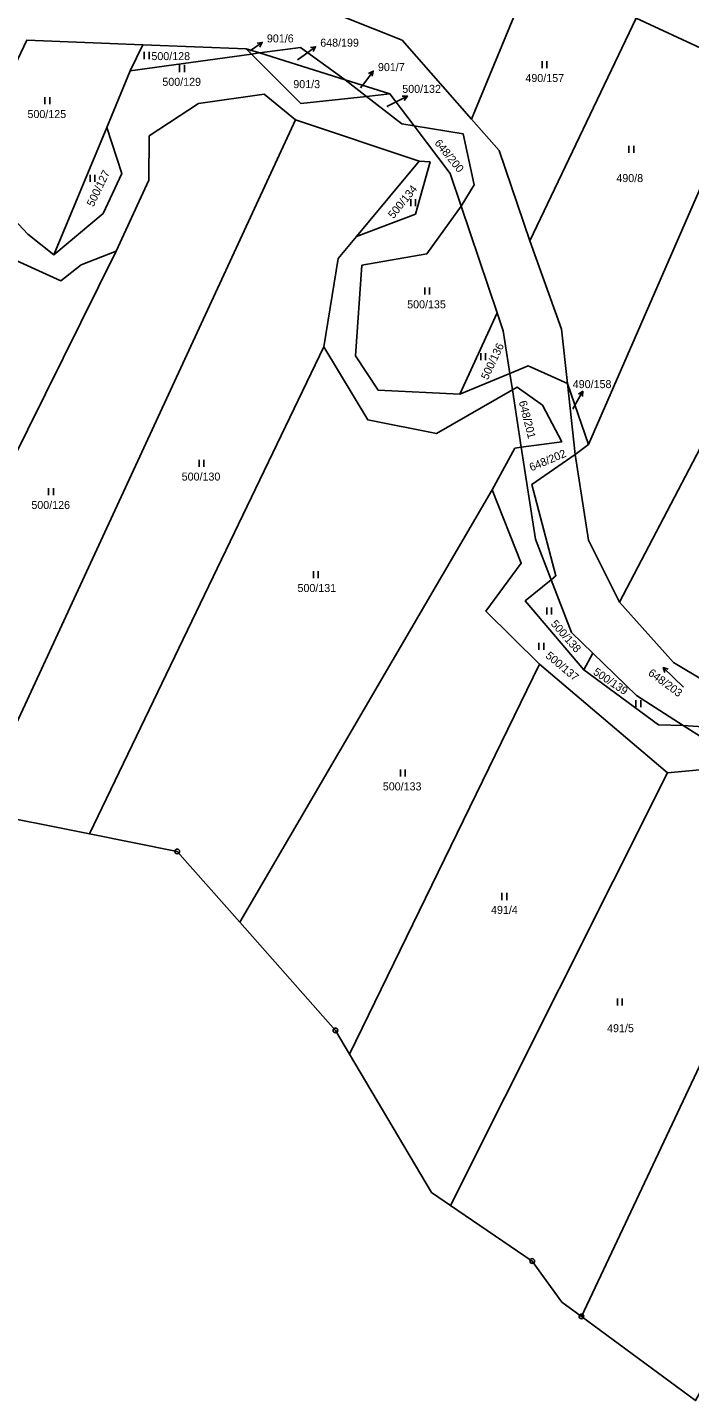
# Model space of a CAD drawing. Extents: x -654083 to -650132, y -1099819 to -1096699.
# Drawn here: x -650469.7 to -650329, y -1099108.4 to -1098816.8 of the extents above; entities that cross this region are included whole.
import ezdxf

# ---------------------------------------------------------------- set-up
doc = ezdxf.new("R2010")
doc.units = 0
for name, color, linetype in [('Geodetické body', 7, 'Continuous'), ('Obvody jako plochy', 7, 'Continuous'), ('Parcelní čísla', 7, 'Continuous'), ('Prvky pro prodl_ par_ č_', 7, 'Continuous'), ('Značky kultur', 7, 'Continuous')]:
    doc.layers.add(name, color=color, linetype=linetype)

msp = doc.modelspace()

# ---------------------------------------------------------------- linework, layer by layer
at = {"layer": 'Geodetické body'}
for centre, radius in [((-650437.89, -1098991.78), 0.5), ((-650437.89, -1098991.78), 0.001), ((-650404.24, -1099029.82), 0.5), ((-650404.24, -1099029.82), 0.001), ((-650362.41, -1099078.79), 0.5), ((-650362.41, -1099078.79), 0.001), ((-650351.95, -1099090.56), 0.5), ((-650351.95, -1099090.56), 0.5), ((-650351.95, -1099090.56), 0.001), ((-650351.95, -1099090.56), 0.001)]:
    msp.add_circle(centre, radius, dxfattribs=at)
at = {"layer": 'Obvody jako plochy'}
for points in [[(-650359.84, -1098798.83), (-650375.33, -1098836.22), (-650390.08, -1098819.48), (-650407.38, -1098812.55), (-650376.79, -1098746.23)], [(-650303.75, -1098798.96), (-650315.83, -1098826.13), (-650340.3, -1098814.8), (-650321.58, -1098776.26)], [(-650359.84, -1098798.83), (-650357.31, -1098806.74), (-650340.3, -1098814.8), (-650362.89, -1098862.05), (-650369.42, -1098842.92), (-650375.33, -1098836.22)], [(-650340.3, -1098814.8), (-650315.83, -1098826.13), (-650350.43, -1098905.37), (-650354.89, -1098892.38), (-650356.22, -1098880.84), (-650362.89, -1098862.05)], [(-650478.84, -1098838.29), (-650475.67, -1098854.31), (-650469.69, -1098860.68), (-650464.15, -1098865.04), (-650452.84, -1098838.04), (-650447.9, -1098825.96), (-650445.19, -1098820.41), (-650469.84, -1098819.44)], [(-650423.24, -1098821.28), (-650422.11, -1098822.41), (-650447.9, -1098825.96), (-650445.19, -1098820.41)], [(-650422.11, -1098822.41), (-650420.4, -1098822.17), (-650423.24, -1098821.28)], [(-650402.2, -1098827.88), (-650397.65, -1098831.4), (-650411.63, -1098832.89), (-650422.11, -1098822.41), (-650420.4, -1098822.17)], [(-650402.2, -1098827.88), (-650420.4, -1098822.17), (-650411.67, -1098821)], [(-650397.65, -1098831.4), (-650392.68, -1098830.87), (-650402.2, -1098827.88)], [(-650290.82, -1098837.74), (-650343.84, -1098938.87), (-650350.47, -1098925.67), (-650353.29, -1098907.45), (-650350.43, -1098905.37), (-650315.83, -1098826.13)], [(-650433.34, -1098832.92), (-650443.85, -1098839.8), (-650443.92, -1098849.21), (-650450.86, -1098864.25), (-650507.26, -1098977.91), (-650480.76, -1098983.21), (-650412.75, -1098836.35), (-650419.42, -1098830.91)], [(-650387.53, -1098837.66), (-650392.68, -1098830.87), (-650397.65, -1098831.4), (-650390.14, -1098837.2)], [(-650406.73, -1098884.63), (-650456.56, -1098988.05), (-650480.76, -1098983.21), (-650412.75, -1098836.35), (-650386.45, -1098845.14), (-650399.77, -1098861.14), (-650403.69, -1098865.85)], [(-650452.84, -1098838.04), (-650449.66, -1098847.81), (-650453.61, -1098856.26), (-650464.15, -1098865.04)], [(-650374.77, -1098850.18), (-650377.53, -1098854.69), (-650379.86, -1098847.79), (-650387.53, -1098837.66), (-650377.08, -1098839.36)], [(-650318.99, -1098959.66), (-650269.18, -1098859.4), (-650278.46, -1098843.49), (-650290.82, -1098837.74), (-650343.84, -1098938.87), (-650332.36, -1098951.66)], [(-650386.45, -1098845.14), (-650384.14, -1098845.28), (-650387.26, -1098856.38), (-650399.77, -1098861.14)], [(-650377.78, -1098894.64), (-650369.88, -1098877.34), (-650377.53, -1098854.69), (-650384.82, -1098864.84), (-650398.63, -1098867.28), (-650399.99, -1098886.51), (-650395.2, -1098893.82)], [(-650462.64, -1098870.55), (-650475.22, -1098864.86), (-650479.77, -1098859.03), (-650527.83, -1098960.74), (-650523.7, -1098954.28), (-650514.31, -1098960.25), (-650515.6, -1098976.12), (-650507.26, -1098977.91), (-650450.86, -1098864.25), (-650458.31, -1098867.15)], [(-650367.17, -1098890.27), (-650368.57, -1098881.21), (-650369.88, -1098877.34), (-650377.78, -1098894.64)], [(-650424.57, -1099006.83), (-650370.96, -1098915), (-650366.09, -1098906.14), (-650364.76, -1098905.94), (-650366.64, -1098893.73), (-650382.74, -1098903.02), (-650397.37, -1098900.12), (-650406.73, -1098884.63), (-650456.56, -1098988.05), (-650437.89, -1098991.78)], [(-650362.5, -1098913.83), (-650357.38, -1098933.23), (-650358.42, -1098934.08), (-650361.75, -1098925.45), (-650364.76, -1098905.94), (-650356.12, -1098904.81), (-650360.2, -1098897), (-650365.62, -1098893.14), (-650366.64, -1098893.73), (-650367.17, -1098890.27), (-650363.25, -1098888.66), (-650354.89, -1098892.38), (-650353.29, -1098907.45)], [(-650350.43, -1098905.37), (-650353.29, -1098907.45), (-650354.89, -1098892.38)], [(-650365.62, -1098893.14), (-650366.64, -1098893.73), (-650364.76, -1098905.94), (-650356.12, -1098904.81), (-650360.2, -1098897)], [(-650335.57, -1098964.86), (-650330.32, -1098965), (-650316.9, -1098973.53), (-650333.65, -1098975.09), (-650360.84, -1098952.04), (-650372.26, -1098940.76), (-650364.74, -1098930.54), (-650370.96, -1098915), (-650366.09, -1098906.14), (-650364.76, -1098905.94), (-650361.75, -1098925.45), (-650358.42, -1098934.08), (-650363.88, -1098938.56), (-650351.43, -1098953.23)], [(-650268.77, -1099000.15), (-650261.34, -1099007.71), (-650248.3, -1099015.54), (-650238.83, -1099005.17), (-650291.27, -1098976.26), (-650318.99, -1098959.66), (-650332.36, -1098951.66), (-650343.84, -1098938.87), (-650350.47, -1098925.67), (-650353.29, -1098907.45), (-650362.5, -1098913.83), (-650357.38, -1098933.23), (-650358.42, -1098934.08), (-650354.09, -1098945.27), (-650349.55, -1098949.67), (-650340.24, -1098958.69), (-650330.32, -1098965), (-650321.9, -1098965.62), (-650311.24, -1098971.58), (-650308.57, -1098978.96), (-650297.89, -1098985.94), (-650289.44, -1098990.97), (-650287.08, -1098988.66)], [(-650360.84, -1098952.04), (-650401.25, -1099034.86), (-650404.24, -1099029.82), (-650424.57, -1099006.83), (-650370.96, -1098915), (-650364.74, -1098930.54), (-650372.26, -1098940.76)], [(-650354.09, -1098945.27), (-650358.42, -1098934.08), (-650363.88, -1098938.56), (-650351.43, -1098953.23), (-650349.55, -1098949.67)], [(-650330.32, -1098965), (-650340.24, -1098958.69), (-650349.55, -1098949.67), (-650351.43, -1098953.23), (-650335.57, -1098964.86)], [(-650333.65, -1098975.09), (-650379.8, -1099066.99), (-650383.86, -1099064.24), (-650401.25, -1099034.86), (-650360.84, -1098952.04)], [(-650308.57, -1098978.96), (-650316.9, -1098973.53), (-650330.32, -1098965), (-650321.9, -1098965.62), (-650311.24, -1098971.58)], [(-650312.23, -1099006.49), (-650351.95, -1099090.56), (-650356.09, -1099087.51), (-650362.41, -1099078.79), (-650379.8, -1099066.99), (-650333.65, -1098975.09), (-650316.9, -1098973.53)], [(-650299.64, -1099011.71), (-650312.23, -1099006.49), (-650351.95, -1099090.56), (-650327.69, -1099108.43), (-650270.13, -1099006.07), (-650285.42, -1098994.55)]]:
    msp.add_lwpolyline(points, close=True, dxfattribs=at)
for points in [[(-650469.84, -1098819.44), (-650445.19, -1098820.41), (-650423.24, -1098821.28), (-650420.4, -1098822.17), (-650411.67, -1098821), (-650402.2, -1098827.88), (-650392.68, -1098830.87), (-650387.53, -1098837.66), (-650377.08, -1098839.36), (-650374.77, -1098850.18), (-650377.53, -1098854.69), (-650369.88, -1098877.34), (-650368.57, -1098881.21), (-650367.17, -1098890.27), (-650363.25, -1098888.66), (-650354.89, -1098892.38), (-650356.22, -1098880.84), (-650362.89, -1098862.05), (-650369.42, -1098842.92), (-650375.33, -1098836.22), (-650390.08, -1098819.48), (-650407.38, -1098812.55)], [(-650475.67, -1098854.31), (-650469.69, -1098860.68), (-650464.15, -1098865.04), (-650453.61, -1098856.26), (-650449.66, -1098847.81), (-650452.84, -1098838.04), (-650447.9, -1098825.96), (-650422.11, -1098822.41), (-650411.63, -1098832.89), (-650397.65, -1098831.4), (-650390.14, -1098837.2), (-650387.53, -1098837.66), (-650379.86, -1098847.79), (-650377.53, -1098854.69), (-650384.82, -1098864.84), (-650398.63, -1098867.28), (-650399.99, -1098886.51), (-650395.2, -1098893.82), (-650377.78, -1098894.64), (-650367.17, -1098890.27), (-650366.64, -1098893.73), (-650382.74, -1098903.02), (-650397.37, -1098900.12), (-650406.73, -1098884.63), (-650403.69, -1098865.85), (-650399.77, -1098861.14), (-650387.26, -1098856.38), (-650384.14, -1098845.28), (-650386.45, -1098845.14), (-650412.75, -1098836.35), (-650419.42, -1098830.91), (-650433.34, -1098832.92), (-650443.85, -1098839.8), (-650443.92, -1098849.21), (-650450.86, -1098864.25), (-650458.31, -1098867.15), (-650462.64, -1098870.55), (-650475.22, -1098864.86)]]:
    msp.add_lwpolyline(points, dxfattribs=at)
at = {"layer": 'Prvky pro prodl_ par_ č_'}
for p, q in [((-650422.28, -1098821.65), (-650419.82, -1098819.93)), ((-650422.43, -1098821.75), (-650422.28, -1098821.65)), ((-650412.31, -1098823.64), (-650410.9, -1098822.61)), ((-650410.9, -1098822.61), (-650408.48, -1098820.84)), ((-650398.89, -1098829.6), (-650398.01, -1098828.42)), ((-650398.01, -1098828.42), (-650396.21, -1098826.02)), ((-650391.62, -1098832.7), (-650388.95, -1098831.34)), ((-650393.33, -1098833.57), (-650391.62, -1098832.7)), ((-650353.15, -1098896.62), (-650351.66, -1098894.02)), ((-650353.8, -1098897.75), (-650353.15, -1098896.62))]:
    msp.add_line(p, q, dxfattribs=at)
for points in [[(-650420.93, -1098820.1), (-650419.82, -1098819.93), (-650420.35, -1098820.92)], [(-650409.58, -1098821.03), (-650408.48, -1098820.84), (-650408.99, -1098821.83)], [(-650397.21, -1098826.52), (-650396.21, -1098826.02), (-650396.41, -1098827.12)], [(-650390.06, -1098831.35), (-650388.95, -1098831.34), (-650389.61, -1098832.24)], [(-650352.59, -1098894.64), (-650351.66, -1098894.02), (-650351.72, -1098895.13)]]:
    msp.add_lwpolyline(points, dxfattribs=at)
at = {"layer": 'Značky kultur'}
for p, q in [((-650444.9, -1098821.96), (-650444.9, -1098823.46)), ((-650443.88, -1098823.46), (-650443.88, -1098821.96)), ((-650437.38, -1098824.72), (-650437.38, -1098826.22)), ((-650436.35, -1098826.22), (-650436.35, -1098824.72)), ((-650360.32, -1098823.92), (-650360.32, -1098825.42)), ((-650359.3, -1098825.42), (-650359.3, -1098823.92)), ((-650466.02, -1098831.56), (-650466.02, -1098833.06)), ((-650464.99, -1098833.06), (-650464.99, -1098831.56)), ((-650341.86, -1098841.89), (-650341.86, -1098843.39)), ((-650340.83, -1098843.39), (-650340.83, -1098841.89)), ((-650456.41, -1098848.03), (-650456.41, -1098849.53)), ((-650455.39, -1098849.53), (-650455.39, -1098848.03)), ((-650388.24, -1098853.25), (-650388.24, -1098854.75)), ((-650387.21, -1098854.75), (-650387.21, -1098853.25)), ((-650385.28, -1098871.99), (-650385.28, -1098873.49)), ((-650384.26, -1098873.49), (-650384.26, -1098871.99)), ((-650373.37, -1098885.92), (-650373.37, -1098887.42)), ((-650372.34, -1098887.42), (-650372.34, -1098885.92)), ((-650433.23, -1098908.57), (-650433.23, -1098910.07)), ((-650432.2, -1098910.07), (-650432.2, -1098908.57)), ((-650465.23, -1098914.6), (-650465.23, -1098916.1)), ((-650464.2, -1098916.1), (-650464.2, -1098914.6)), ((-650408.94, -1098932.25), (-650408.94, -1098933.75)), ((-650407.92, -1098933.75), (-650407.92, -1098932.25)), ((-650359.31, -1098939.97), (-650359.31, -1098941.47)), ((-650358.29, -1098941.47), (-650358.29, -1098939.97)), ((-650360.98, -1098947.46), (-650360.98, -1098948.96)), ((-650359.95, -1098948.96), (-650359.95, -1098947.46)), ((-650330.23, -1098956.86), (-650334.57, -1098952.72)), ((-650340.36, -1098959.67), (-650340.36, -1098961.17)), ((-650339.33, -1098961.17), (-650339.33, -1098959.67)), ((-650390.42, -1098974.39), (-650390.42, -1098975.89)), ((-650389.4, -1098975.89), (-650389.4, -1098974.39)), ((-650368.86, -1099000.61), (-650368.86, -1099002.11)), ((-650367.83, -1099002.11), (-650367.83, -1099000.61)), ((-650344.29, -1099023.04), (-650344.29, -1099024.54)), ((-650343.27, -1099024.54), (-650343.27, -1099023.04))]:
    msp.add_line(p, q, dxfattribs=at)
msp.add_lwpolyline([(-650334.19, -1098953.77), (-650334.57, -1098952.72), (-650333.5, -1098953.05)], dxfattribs=at)

# ---------------------------------------------------------------- texts
at = {"layer": 'Parcelní čísla'}
for s, p in [('500/128', (-650443.38, -1098823.69)), ('500/129', (-650441.05, -1098829.15)), ('901/3', (-650413.21, -1098829.64)), ('490/157', (-650363.86, -1098828.35)), ('500/125', (-650469.73, -1098836)), ('490/8', (-650344.52, -1098849.6)), ('500/135', (-650389, -1098876.42)), ('500/130', (-650436.94, -1098913.01)), ('500/126', (-650468.9, -1098919.04)), ('500/131', (-650412.32, -1098936.68)), ('500/133', (-650394.18, -1098978.82)), ('491/4', (-650371.17, -1099005.05)), ('491/5', (-650346.49, -1099030.18))]:
    msp.add_text(s, height=1.7, dxfattribs=at).set_placement(p)
for s, height, rotation, p in [('901/6', 0.1, 343.188, (-650422.43, -1098821.75)), ('648/199', 0.1, 342.567, (-650412.31, -1098823.64)), ('901/7', 0.1, 323.748, (-650398.89, -1098829.6)), ('500/132', 0.1, 323.748, (-650393.33, -1098833.57)), ('648/200', 1.7, 309.087, (-650383.3, -1098841.36)), ('500/127', 1.7, 64.197, (-650455.71, -1098854.97)), ('500/134', 1.7, 50.94, (-650391.92, -1098857.49)), ('500/136', 1.7, 64.728, (-650371.87, -1098891.74)), ('648/201', 1.7, 284.13, (-650365.27, -1098896.26)), ('490/158', 0.1, 276.822, (-650353.8, -1098897.75)), ('648/202', 1.7, 22.887, (-650362.59, -1098911.07)), ('500/138', 1.7, 311.238, (-650358.57, -1098943.53)), ('500/137', 1.7, 320.211, (-650359.72, -1098950.47)), ('500/139', 1.7, 326.043, (-650349.62, -1098954.04)), ('648/203', 1.7, 323.523, (-650337.91, -1098954.2))]:
    msp.add_text(s, height=height, rotation=rotation, dxfattribs=at).set_placement(p)
at = {"layer": 'Prvky pro prodl_ par_ č_'}
for s, p in [('901/6', (-650418.82, -1098819.93)), ('648/199', (-650407.48, -1098820.84)), ('901/7', (-650395.21, -1098826.02)), ('500/132', (-650390.04, -1098830.65)), ('490/158', (-650353.79, -1098893.37))]:
    msp.add_text(s, height=1.7, dxfattribs=at).set_placement(p)

doc.saveas('drawing.dxf')
